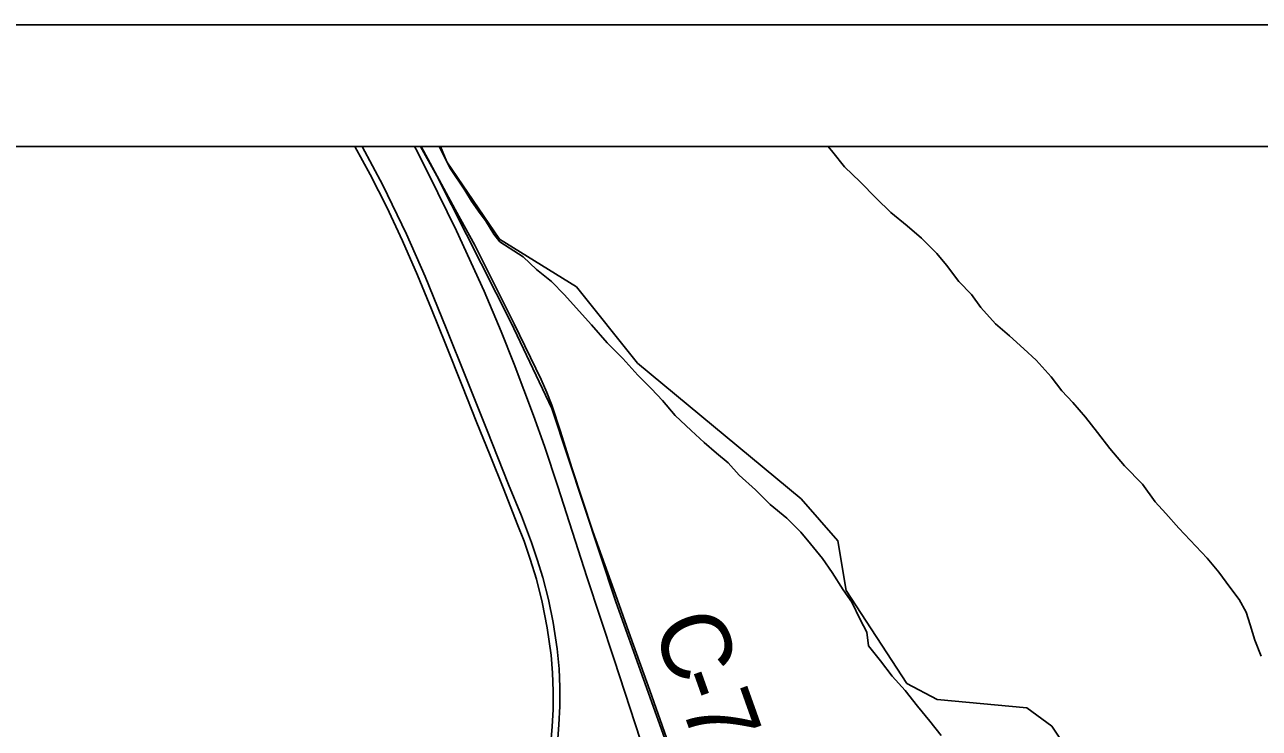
# Model space of a CAD drawing. Extents: x 0 to 34, y 0 to 22.
# Drawn here: x 7.482 to 8.494, y 20.423 to 21 of the extents above; entities that cross this region are included whole.
import ezdxf

# ---------------------------------------------------------------- set-up
doc = ezdxf.new("R2010")
doc.units = 0
for name, color, linetype in [('Default', 7, 'Continuous'), ('GM_X_County_Road', 7, 'Continuous'), ('GM_X_County_Road_Text', 7, 'Continuous'), ('GM_X_Major_River', 7, 'Continuous'), ('GM_X_Rail_Line', 7, 'Continuous'), ('GM_X_State_Route', 7, 'Continuous'), ('SH_Cut_Line', 7, 'Continuous'), ('SH_Data', 7, 'Continuous')]:
    doc.layers.add(name, color=color, linetype=linetype)

msp = doc.modelspace()

# ---------------------------------------------------------------- linework, layer by layer
at = {"layer": 'Default'}
for p, q in [((7.8225, 20.9), (2.1, 20.9)), ((7.8279, 20.8874), (7.8225, 20.9)), ((7.8709, 20.824), (7.8279, 20.8874)), ((7.9341, 20.7849), (7.8709, 20.824)), ((7.984, 20.7223), (7.9341, 20.7849)), ((8.1182, 20.6111), (7.984, 20.7223)), ((8.1484, 20.5766), (8.1182, 20.6111)), ((8.1552, 20.5359), (8.1484, 20.5766)), ((8.205, 20.4597), (8.1552, 20.5359)), ((8.2298, 20.4464), (8.205, 20.4597)), ((8.3034, 20.4395), (8.2298, 20.4464)), ((8.3237, 20.4245), (8.3034, 20.4395)), ((8.3529, 20.3814), (8.3237, 20.4245))]:
    msp.add_line(p, q, dxfattribs=at)
at = {"layer": 'GM_X_County_Road'}
for p, q in [((7.8346, 20.8483), (7.8068, 20.9)), ((7.8508, 20.8192), (7.8346, 20.8483)), ((7.8615, 20.7979), (7.8508, 20.8192)), ((7.883, 20.7545), (7.8615, 20.7979)), ((7.9052, 20.7089), (7.883, 20.7545)), ((7.9099, 20.6984), (7.9052, 20.7089)), ((7.9138, 20.6879), (7.9099, 20.6984)), ((7.921, 20.6664), (7.9138, 20.6879)), ((7.9303, 20.6365), (7.921, 20.6664)), ((7.9474, 20.5844), (7.9303, 20.6365)), ((7.9646, 20.5364), (7.9474, 20.5844)), ((7.9784, 20.4978), (7.9646, 20.5364)), ((7.9943, 20.4538), (7.9784, 20.4978)), ((8.008, 20.4149), (7.9943, 20.4538))]:
    msp.add_line(p, q, dxfattribs=at)
at = {"layer": 'GM_X_Major_River'}
for p, q in [((7.8215, 20.9), (7.8307, 20.8817)), ((8.1442, 20.8953), (8.1404, 20.9)), ((8.1539, 20.8834), (8.1442, 20.8953)), ((7.8307, 20.8817), (7.8425, 20.8642)), ((8.1666, 20.8711), (8.1539, 20.8834)), ((8.1798, 20.8577), (8.1666, 20.8711)), ((7.8425, 20.8642), (7.8481, 20.8551)), ((7.8481, 20.8551), (7.8551, 20.8451)), ((8.1918, 20.8458), (8.1798, 20.8577)), ((7.8551, 20.8451), (7.8594, 20.8394)), ((7.8594, 20.8394), (7.8664, 20.8281)), ((8.2052, 20.835), (8.1918, 20.8458)), ((8.2168, 20.825), (8.2052, 20.835)), ((7.8664, 20.8281), (7.8712, 20.822)), ((7.8712, 20.822), (7.8904, 20.8097)), ((8.2295, 20.8124), (8.2168, 20.825)), ((7.8904, 20.8097), (7.9012, 20.7993)), ((8.2373, 20.8026), (8.2295, 20.8124)), ((7.9012, 20.7993), (7.9136, 20.7893)), ((8.2474, 20.7892), (8.2373, 20.8026)), ((7.9136, 20.7893), (7.9244, 20.7785)), ((8.2579, 20.7788), (8.2474, 20.7892)), ((7.9244, 20.7785), (7.9364, 20.7651)), ((8.2656, 20.7679), (8.2579, 20.7788)), ((8.2776, 20.7545), (8.2656, 20.7679)), ((7.9364, 20.7651), (7.9465, 20.7539)), ((7.9465, 20.7539), (7.9593, 20.739)), ((8.2892, 20.7448), (8.2776, 20.7545)), ((7.9593, 20.739), (7.972, 20.7263)), ((8.3008, 20.7341), (8.2892, 20.7448)), ((8.3108, 20.7248), (8.3008, 20.7341)), ((7.972, 20.7263), (7.9844, 20.7125)), ((8.3232, 20.711), (8.3108, 20.7248)), ((7.9844, 20.7125), (7.9956, 20.7013)), ((8.3321, 20.6997), (8.3232, 20.711)), ((7.9956, 20.7013), (8.0045, 20.6916)), ((8.341, 20.6901), (8.3321, 20.6997)), ((8.0045, 20.6916), (8.015, 20.6793)), ((8.3515, 20.6781), (8.341, 20.6901)), ((8.015, 20.6793), (8.0281, 20.6671)), ((8.3612, 20.6654), (8.3515, 20.6781)), ((8.0281, 20.6671), (8.0389, 20.6574)), ((8.0389, 20.6574), (8.0489, 20.6485)), ((8.3713, 20.6523), (8.3612, 20.6654)), ((8.0489, 20.6485), (8.0585, 20.6407)), ((8.3833, 20.6381), (8.3713, 20.6523)), ((8.0585, 20.6407), (8.0674, 20.6306)), ((8.398, 20.6232), (8.3833, 20.6381)), ((8.0674, 20.6306), (8.0809, 20.6184)), ((8.0809, 20.6184), (8.0929, 20.6065)), ((8.4085, 20.6086), (8.398, 20.6232)), ((8.0929, 20.6065), (8.1064, 20.5953)), ((8.4171, 20.5989), (8.4085, 20.6086)), ((8.4279, 20.587), (8.4171, 20.5989)), ((8.1064, 20.5953), (8.118, 20.5838)), ((8.4418, 20.5721), (8.4279, 20.587)), ((8.118, 20.5838), (8.1258, 20.5741)), ((8.1258, 20.5741), (8.1358, 20.5621)), ((8.4511, 20.5624), (8.4418, 20.5721)), ((8.1358, 20.5621), (8.1436, 20.5505)), ((8.4608, 20.5508), (8.4511, 20.5624)), ((8.1436, 20.5505), (8.1528, 20.5364)), ((8.4698, 20.5385), (8.4608, 20.5508)), ((8.1528, 20.5364), (8.1598, 20.5264)), ((8.4772, 20.5284), (8.4698, 20.5385)), ((8.1598, 20.5264), (8.1667, 20.512)), ((8.483, 20.5182), (8.4772, 20.5284)), ((8.4863, 20.5077), (8.483, 20.5182)), ((8.1667, 20.512), (8.1722, 20.5017)), ((8.4903, 20.4952), (8.4863, 20.5077)), ((8.1722, 20.5017), (8.1736, 20.4904)), ((8.4955, 20.4821), (8.4903, 20.4952)), ((8.1736, 20.4904), (8.1833, 20.4781)), ((8.1833, 20.4781), (8.193, 20.4657)), ((8.193, 20.4657), (8.2035, 20.4538)), ((8.2035, 20.4538), (8.2136, 20.4411)), ((8.2136, 20.4411), (8.2237, 20.4287)), ((8.2237, 20.4287), (8.233, 20.4168))]:
    msp.add_line(p, q, dxfattribs=at)
at = {"layer": 'GM_X_Rail_Line'}
for p, q in [((7.8031, 20.8968), (7.8014, 20.9)), ((7.8062, 20.9), (7.8197, 20.8759)), ((7.8205, 20.8622), (7.8031, 20.8968)), ((7.8197, 20.8759), (7.8804, 20.7559)), ((7.8358, 20.8308), (7.8205, 20.8622)), ((7.8585, 20.7813), (7.8358, 20.8308)), ((7.8724, 20.7482), (7.8585, 20.7813)), ((7.8829, 20.7214), (7.8724, 20.7482)), ((7.8804, 20.7559), (7.9138, 20.6851)), ((7.8988, 20.6793), (7.8829, 20.7214)), ((7.9079, 20.6542), (7.8988, 20.6793)), ((7.9138, 20.6851), (7.9664, 20.5265)), ((7.9187, 20.6212), (7.9079, 20.6542)), ((7.9426, 20.5472), (7.9187, 20.6212)), ((7.965, 20.4793), (7.9426, 20.5472)), ((7.9664, 20.5265), (8.035, 20.3342)), ((7.9983, 20.3771), (7.965, 20.4793))]:
    msp.add_line(p, q, dxfattribs=at)
at = {"layer": 'GM_X_State_Route'}
for p, q in [((7.7649, 20.877), (7.7523, 20.9)), ((7.7754, 20.8683), (7.7584, 20.9)), ((7.7785, 20.8502), (7.7649, 20.877)), ((7.7948, 20.8282), (7.7754, 20.8683)), ((7.7915, 20.8227), (7.7785, 20.8502)), ((7.8037, 20.7945), (7.7915, 20.8227)), ((7.81, 20.7933), (7.7948, 20.8282)), ((7.8152, 20.7667), (7.8037, 20.7945)), ((7.8272, 20.751), (7.81, 20.7933)), ((7.8266, 20.7383), (7.8152, 20.7667)), ((7.844, 20.7094), (7.8272, 20.751)), ((7.8406, 20.7032), (7.8266, 20.7383)), ((7.8609, 20.6671), (7.844, 20.7094)), ((7.8519, 20.6748), (7.8406, 20.7032)), ((7.8634, 20.6465), (7.8519, 20.6748)), ((7.8785, 20.6229), (7.8609, 20.6671)), ((7.8745, 20.6187), (7.8634, 20.6465)), ((7.8856, 20.5906), (7.8745, 20.6187)), ((7.8889, 20.5972), (7.8785, 20.6229)), ((7.8972, 20.5753), (7.8889, 20.5972)), ((7.8911, 20.5764), (7.8856, 20.5906)), ((7.8962, 20.5616), (7.8911, 20.5764)), ((7.902, 20.5613), (7.8972, 20.5753)), ((7.9014, 20.5452), (7.8962, 20.5616)), ((7.9064, 20.5466), (7.902, 20.5613)), ((7.9061, 20.5263), (7.9014, 20.5452)), ((7.9112, 20.5284), (7.9064, 20.5466)), ((7.9101, 20.5052), (7.9061, 20.5263)), ((7.915, 20.5095), (7.9112, 20.5284)), ((7.9133, 20.4829), (7.9101, 20.5052)), ((7.9184, 20.4879), (7.915, 20.5095)), ((7.9198, 20.4715), (7.9184, 20.4879)), ((7.9145, 20.4682), (7.9133, 20.4829)), ((7.9151, 20.4534), (7.9145, 20.4682)), ((7.9204, 20.4565), (7.9198, 20.4715)), ((7.9204, 20.441), (7.9204, 20.4565)), ((7.9149, 20.4383), (7.9151, 20.4534)), ((7.9143, 20.4242), (7.9149, 20.4383)), ((7.9197, 20.4258), (7.9204, 20.441)), ((7.9129, 20.4077), (7.9143, 20.4242)), ((7.9185, 20.4107), (7.9197, 20.4258))]:
    msp.add_line(p, q, dxfattribs=at)
at = {"layer": 'SH_Cut_Line'}
for p, q in [((7.8225, 20.9), (2.1, 20.9)), ((7.8279, 20.8874), (7.8225, 20.9)), ((7.8709, 20.824), (7.8279, 20.8874)), ((7.9341, 20.7849), (7.8709, 20.824)), ((7.984, 20.7223), (7.9341, 20.7849)), ((8.1182, 20.6111), (7.984, 20.7223)), ((8.1484, 20.5766), (8.1182, 20.6111)), ((8.1552, 20.5359), (8.1484, 20.5766)), ((8.205, 20.4597), (8.1552, 20.5359)), ((8.2298, 20.4464), (8.205, 20.4597)), ((8.3034, 20.4395), (8.2298, 20.4464)), ((8.3237, 20.4245), (8.3034, 20.4395)), ((8.3529, 20.3814), (8.3237, 20.4245))]:
    msp.add_line(p, q, dxfattribs=at)
at = {"layer": 'SH_Data'}
for p, q in [((2, 21), (9, 21)), ((2.1, 20.9), (8.9, 20.9))]:
    msp.add_line(p, q, dxfattribs=at)

# ---------------------------------------------------------------- texts
at = {"layer": 'GM_X_County_Road_Text'}
for s, rotation, p in [('C', 289.5778, (7.996, 20.5077)), ('-', 289.5779, (8.0116, 20.4641)), ('7', 289.5858, (8.0193, 20.4423))]:
    msp.add_text(s, height=0.0568, rotation=rotation, dxfattribs=at).set_placement(p)

doc.saveas('drawing.dxf')
